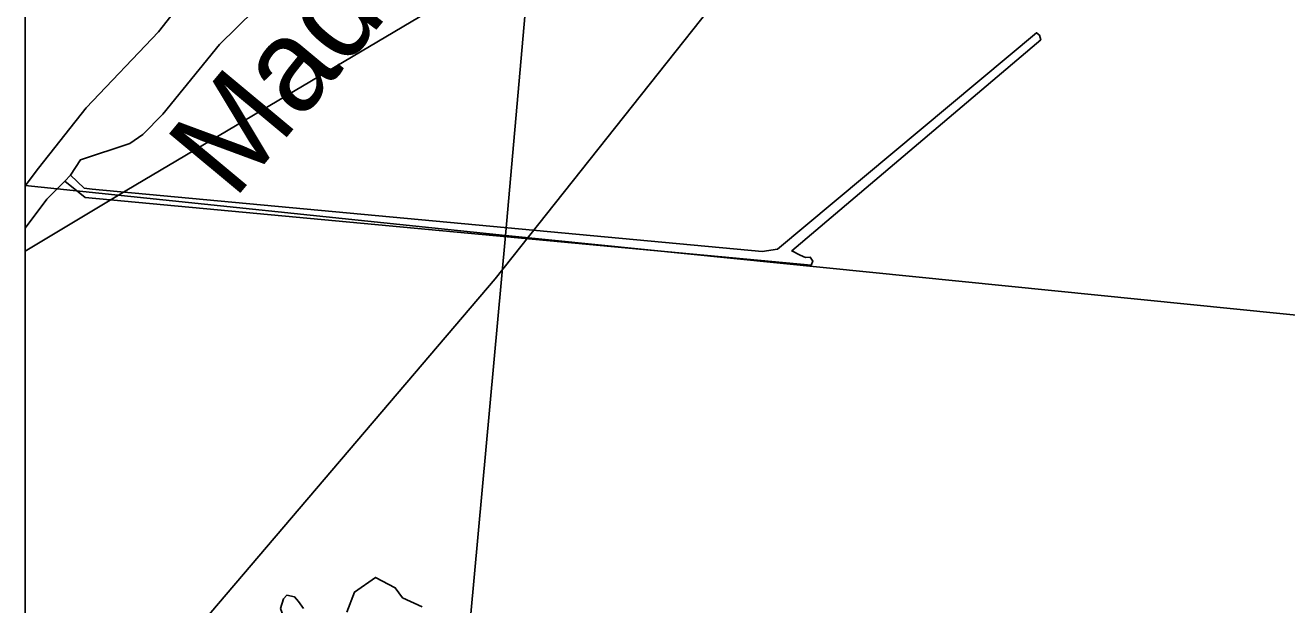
# Model space of a CAD drawing. Extents: x 0 to 34, y 0 to 22.
# Drawn here: x 22.516 to 23.805, y 16.574 to 17.166 of the extents above; entities that cross this region are included whole.
import ezdxf

# ---------------------------------------------------------------- set-up
doc = ezdxf.new("R2010")
doc.units = 0
for name, color, linetype in [('GM_X_County_Road', 7, 'Continuous'), ('GM_X_Major_River', 7, 'Continuous'), ('GM_X_Major_River_Text', 7, 'Continuous'), ('GM_X_Minor_Lake', 7, 'Continuous'), ('GM_X_Minor_River', 7, 'Continuous'), ('GM_X_Rail_Line', 7, 'Continuous'), ('GM_X_Section', 7, 'Continuous'), ('SH_Border', 7, 'Continuous'), ('SH_Data', 7, 'Continuous')]:
    doc.layers.add(name, color=color, linetype=linetype)

msp = doc.modelspace()

# ---------------------------------------------------------------- linework, layer by layer
at = {"layer": 'GM_X_County_Road'}
for points in [[(22.5164, 18.0167), (22.5164, 17.0024), (23.007, 16.9513), (23.096, 17.9586)], [(22.5164, 17.0024), (22.5164, 15.9857), (22.9154, 15.9508), (23.007, 16.9513)]]:
    msp.add_lwpolyline(points, close=True, dxfattribs=at)
at = {"layer": 'GM_X_Major_River'}
for points in [[(23.3143, 17.6507), (23.2471, 17.5759), (23.2084, 17.5454), (23.1637, 17.5181), (23.1213, 17.4885), (22.9849, 17.4068), (22.9381, 17.3709), (22.9054, 17.3395), (22.8788, 17.3197), (22.8126, 17.2517), (22.7505, 17.1816), (22.7147, 17.1465), (22.6571, 17.0755), (22.6365, 17.0545), (22.6233, 17.0453), (22.5728, 17.0288), (22.5625, 17.0129)], [(22.6913, 17.2094), (22.6524, 17.1596), (22.5788, 17.0818), (22.5298, 17.0201), (22.5164, 17.002)], [(22.557, 17.007), (22.5384, 16.9884), (22.5164, 16.9589)], [(22.5625, 17.0129), (22.557, 17.007)]]:
    msp.add_lwpolyline(points, dxfattribs=at)
at = {"layer": 'GM_X_Minor_Lake'}
for points in [[(22.9218, 16.5716), (22.9019, 16.5807), (22.8945, 16.5911), (22.8743, 16.6018), (22.8527, 16.5867), (22.8451, 16.5663)], [(22.8171, 16.5312), (22.815, 16.5228), (22.8114, 16.5157), (22.8031, 16.5181), (22.7869, 16.5424), (22.7773, 16.5699), (22.7801, 16.5798), (22.7836, 16.5835), (22.7915, 16.5818), (22.7956, 16.5772), (22.8008, 16.5698)]]:
    msp.add_lwpolyline(points, dxfattribs=at)
at = {"layer": 'GM_X_Minor_River'}
for points in [[(22.557, 17.007), (22.5776, 16.9902), (23.3193, 16.9211), (23.3209, 16.9249), (23.3184, 16.9291), (23.3134, 16.9289), (23.3082, 16.9312), (23.2995, 16.9356), (23.5539, 17.1515), (23.5528, 17.1561), (23.5494, 17.1585), (23.2848, 16.9374), (23.2692, 16.9351), (22.5846, 16.9988), (22.5766, 16.9997), (22.5625, 17.0129)], [(22.5625, 17.0129), (22.557, 17.007)]]:
    msp.add_lwpolyline(points, dxfattribs=at)
at = {"layer": 'GM_X_Rail_Line'}
for points in [[(22.5164, 16.9354), (22.6202, 16.9977), (23.2863, 17.3926), (23.9265, 17.9846), (25.2894, 19.3687), (25.6884, 19.7377)], [(22.5164, 16.4015), (22.604, 16.4732), (22.6804, 16.5359), (22.9964, 16.9071), (23.3912, 17.4049), (25.2192, 19.2663), (25.7166, 19.735)]]:
    msp.add_lwpolyline(points, dxfattribs=at)
at = {"layer": 'GM_X_Section'}
for points in [[(24.0891, 17.8588), (23.9842, 16.8529), (23.007, 16.9513), (23.096, 17.9586)], [(23.9842, 16.8529), (23.8855, 15.856), (22.9324, 15.949), (22.9154, 15.9508), (23.007, 16.9513)]]:
    msp.add_lwpolyline(points, close=True, dxfattribs=at)
at = {"layer": 'SH_Border'}
msp.add_lwpolyline([(22.5164, 19.0318), (22.5164, 14.9743)], dxfattribs=at)
at = {"layer": 'SH_Data'}
msp.add_line((22.5164, 20.2618), (22.5164, 13.4618), dxfattribs=at)
msp.add_lwpolyline([(22.5164, 19.0318), (22.5164, 13.4618)], dxfattribs=at)

# ---------------------------------------------------------------- texts
at = {"layer": 'GM_X_Major_River_Text'}
msp.add_text('Mad', height=0.09475, rotation=50.1986, dxfattribs=at).set_placement((22.7295, 16.9868))

doc.saveas('drawing.dxf')
